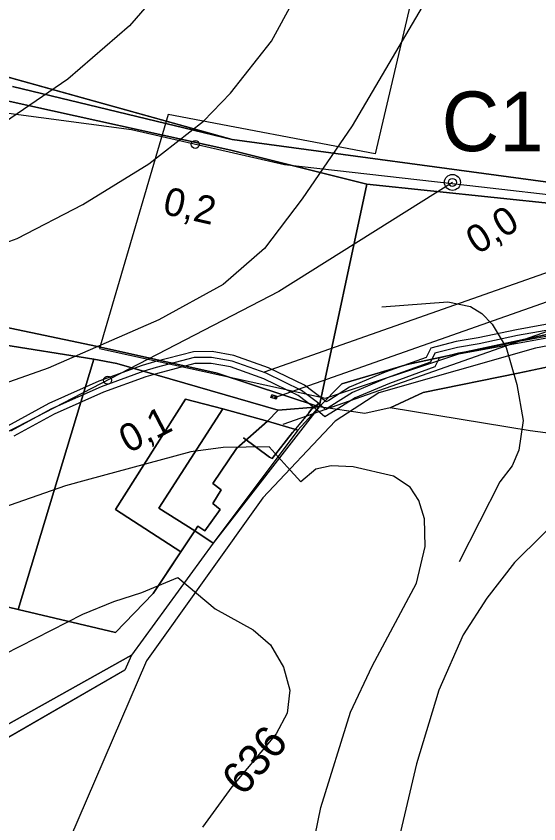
# Model space of a CAD drawing. Extents: x -709418 to -703832, y -1161719 to -1157826.
# Drawn here: x -707328.3 to -707197, y -1160852.4 to -1160649.3 of the extents above; entities that cross this region are included whole.
import ezdxf

# ---------------------------------------------------------------- set-up
doc = ezdxf.new("R2010")
doc.units = 0
for name, color, linetype in [('102_obvod PÚ', 7, 'Continuous'), ('106_zastavitelné plochy', 7, 'Continuous'), ('110_silnice II. třídy a III. třídy', 7, 'Continuous'), ('120_vrstevnice hlavní', 7, 'Continuous'), ('121_vrstevnice hlavní_popis', 7, 'Continuous'), ('122_vrstevnice základní', 7, 'Continuous'), ('124_vrstevnice doplňková', 7, 'Continuous'), ('204_zahrada_KN', 7, 'Continuous'), ('206_TTP_KN', 7, 'Continuous'), ('207_lesní pozemek_KN', 7, 'Continuous'), ('209_zastavěná plocha_KN', 7, 'Continuous'), ('210_ostatní plocha_KN', 7, 'Continuous'), ('301_polní cesta_stav', 7, 'Continuous'), ('302_polní cesta_stav_popis', 7, 'Continuous'), ('311_polní cesta_staničení', 7, 'Continuous'), ('708_el NN nadzemní a podzemní_ E.ON', 7, 'Continuous'), ('717_elektronická komunikace O2', 7, 'Continuous'), ('735_OP sítí TI', 7, 'Continuous'), ('Trasa-Hlavni  staniceni', 7, 'Continuous')]:
    doc.layers.add(name, color=color, linetype=linetype)

# ---------------------------------------------------------------- blocks, each defined once
blk = doc.blocks.new('Elektro - Implicitní$0$NN6301')
for points in [[(0, -0.7), (-0.7, 0)], [(-0.7, -0.7), (-0.7, 0), (0.7, 0), (0.7, -0.7)], [(-0.7, -0.7), (0.7, -0.7)], [(0, -0.7), (0.7, 0)]]:
    blk.add_lwpolyline(points)
blk = doc.blocks.new('_kolecko-HB')
blk.add_circle((0, 0), 0.5)

msp = doc.modelspace()

# ---------------------------------------------------------------- linework, layer by layer
at = {"layer": '102_obvod PÚ'}
for points in [[(-707372.91, -1160652.8), (-707274.07, -1160680.35), (-707329.26, -1160667)], [(-707329.26, -1160667), (-707274.07, -1160680.35), (-707372.91, -1160652.8)], [(-706967.13, -1160843.73), (-707054.56, -1160846.24), (-707070.52, -1160774.23), (-707110.93, -1160765.08), (-707199.13, -1160753.56), (-707234.31, -1160747.78), (-707240.69, -1160749.2), (-707252.18, -1160747.56), (-707262.52, -1160748.35), (-707303.06, -1160736.64), (-707308.84, -1160735.57), (-707327.8, -1160798.49), (-707303.36, -1160804.27), (-707293.87, -1160794.5), (-707283.47, -1160778.71), (-707278.83, -1160781.85), (-707299.31, -1160809.97), (-707301.02, -1160813.75), (-707341.56, -1160837.15), (-707370.67, -1160817.96), (-707379.03, -1160849.56), (-707386.91, -1160884.92)], [(-707327.8, -1160798.49), (-707308.84, -1160735.57), (-707303.06, -1160736.64), (-707262.52, -1160748.35), (-707252.18, -1160747.56), (-707278.83, -1160781.85), (-707283.47, -1160778.71), (-707293.87, -1160794.5), (-707303.36, -1160804.27), (-707327.8, -1160798.49)]]:
    msp.add_lwpolyline(points, dxfattribs=at)
at = {"layer": '106_zastavitelné plochy'}
msp.add_lwpolyline([(-707143.96, -1160643.94), (-707203.3, -1160641.79), (-707228.67, -1160643.51), (-707238.13, -1160683.91), (-707290.16, -1160674.03), (-707307.36, -1160732.91), (-707250.6, -1160745.38), (-707217.06, -1160734.2), (-707117.73, -1160716.15), (-707089.46, -1160706.83), (-707146.29, -1160697.63), (-707149.08, -1160694.92), (-707131.06, -1160645.23), (-707143.96, -1160643.94)], dxfattribs=at)
at = {"layer": '110_silnice II. třídy a III. třídy'}
msp.add_lwpolyline([(-707028.32, -1160686.05), (-707048.83, -1160698.73), (-707085.42, -1160709.51), (-707112.28, -1160716.49), (-707197.84, -1160732.78), (-707237.17, -1160743.98), (-707248.17, -1160751.17), (-707266.36, -1160770.4), (-707295.62, -1160811.38), (-707336.44, -1160906.07)], dxfattribs=at)
at = {"layer": '120_vrstevnice hlavní'}
for points in [[(-707239.58, -1160471.05), (-707235.67, -1160484.94), (-707230.32, -1160508.08), (-707224.97, -1160540.48), (-707222.65, -1160549.74), (-707217.45, -1160563.62), (-707213.4, -1160577.51), (-707212.53, -1160591.4), (-707214.26, -1160609.91), (-707216.87, -1160623.8), (-707221.78, -1160637.68), (-707226.27, -1160646.94), (-707243.92, -1160676.88), (-707256.5, -1160695.25), (-707265.9, -1160707.69), (-707276.32, -1160716.8), (-707292.52, -1160725.63), (-707320.29, -1160737.78), (-707344.3, -1160746.31)], [(-707023.62, -1160699.16), (-707028.9, -1160695.89), (-707035.14, -1160696.56), (-707038.9, -1160689.77), (-707049.51, -1160686.72), (-707065.71, -1160686.28), (-707077.86, -1160687.44), (-707085.96, -1160689.32), (-707098.11, -1160693.52), (-707106.21, -1160697.28), (-707118.36, -1160704.07), (-707123.33, -1160706.91), (-707129.34, -1160709.92), (-707136.11, -1160714.06), (-707134.98, -1160726.48), (-707146.27, -1160736.26), (-707161.76, -1160747.03), (-707168.27, -1160752.24), (-707203.12, -1160786.67), (-707210.07, -1160795.63), (-707216, -1160804.89), (-707222.07, -1160818.78), (-707227.72, -1160837.29), (-707235.38, -1160869.69)]]:
    msp.add_lwpolyline(points, dxfattribs=at)
at = {"layer": '122_vrstevnice základní'}
for points in [[(-707280.22, -1160472.21), (-707271.98, -1160495.64), (-707269.52, -1160504.32), (-707266.62, -1160518.79), (-707265.76, -1160533.25), (-707266.34, -1160554.37), (-707268.79, -1160576.64), (-707275.01, -1160602.1), (-707278.05, -1160611.65), (-707288.03, -1160633.92), (-707295.41, -1160646.65), (-707299.89, -1160651.71), (-707315.37, -1160665.16), (-707351.82, -1160690.04)], [(-707336.49, -1160708.27), (-707328.1, -1160705.23), (-707311.61, -1160696.7), (-707294.97, -1160686.43), (-707281.23, -1160675.72), (-707274.44, -1160668.64), (-707264.17, -1160655.62), (-707258.52, -1160645.2), (-707256.35, -1160640), (-707250.14, -1160620.32), (-707247.53, -1160608.75), (-707246.23, -1160600.07), (-707244.78, -1160574.04), (-707244.64, -1160556.68), (-707246.52, -1160515.6), (-707249.12, -1160502.58), (-707255.78, -1160479.15)], [(-707256.07, -1160869.11), (-707251.73, -1160848.29), (-707244.35, -1160824.27), (-707238.85, -1160812.7), (-707227.71, -1160791.87), (-707225.55, -1160782.62), (-707225.69, -1160775.67), (-707227.14, -1160771.05), (-707229.31, -1160767.72), (-707233.5, -1160764.97), (-707243.63, -1160762.66), (-707249.19, -1160762.37), (-707253.03, -1160763.23), (-707256.79, -1160766.42), (-707260.26, -1160762.66), (-707264.74, -1160757.59), (-707276.32, -1160757.74), (-707284.42, -1160758.89), (-707310.74, -1160765.98), (-707315.95, -1160767.43), (-707338.8, -1160775.38)], [(-707335.33, -1160811.69), (-707311.61, -1160799.68), (-707303.8, -1160796.5), (-707296.72, -1160794.22), (-707287.7, -1160790.45), (-707278.29, -1160798.35), (-707268.79, -1160803.59), (-707264.45, -1160807.35), (-707261.13, -1160812.99), (-707259.54, -1160818.78), (-707260.26, -1160824.56), (-707263.01, -1160829.77), (-707274.15, -1160843.08), (-707281.52, -1160853.2)]]:
    msp.add_lwpolyline(points, dxfattribs=at)
at = {"layer": '124_vrstevnice doplňková'}
msp.add_lwpolyline([(-707236.46, -1160722.37), (-707219.82, -1160721.15), (-707214.12, -1160722.3), (-707211.27, -1160724.03), (-707208.71, -1160726.75), (-707205.18, -1160732.62), (-707202.54, -1160741.96), (-707200.9, -1160750.97), (-707201.99, -1160758.4), (-707203.7, -1160762.37), (-707206.74, -1160766.42), (-707217.01, -1160786.52)], dxfattribs=at)
at = {"layer": '204_zahrada_KN'}
for p, q in [((-707327.8, -1160798.49), (-707308.84, -1160735.57)), ((-707308.84, -1160735.57), (-707303.06, -1160736.64)), ((-707303.06, -1160736.64), (-707262.52, -1160748.35)), ((-707285.78, -1160745.57), (-707303.37, -1160773.36)), ((-707303.37, -1160773.36), (-707285.78, -1160745.57)), ((-707276.36, -1160748), (-707285.78, -1160745.57)), ((-707285.78, -1160745.57), (-707276.36, -1160748)), ((-707276.36, -1160748), (-707292.48, -1160773.03)), ((-707265.13, -1160751.17), (-707276.36, -1160748)), ((-707262.52, -1160748.35), (-707265.13, -1160751.17)), ((-707303.37, -1160773.36), (-707286.95, -1160784)), ((-707286.95, -1160784), (-707303.37, -1160773.36)), ((-707292.48, -1160773.03), (-707283.47, -1160778.71)), ((-707283.47, -1160778.71), (-707286.95, -1160784)), ((-707286.95, -1160784), (-707293.87, -1160794.5)), ((-707293.87, -1160794.5), (-707303.36, -1160804.27)), ((-707303.36, -1160804.27), (-707327.8, -1160798.49))]:
    msp.add_line(p, q, dxfattribs=at)
at = {"layer": '206_TTP_KN'}
for p, q in [((-707274.07, -1160680.35), (-707372.91, -1160652.8)), ((-707330.61, -1160670.57), (-707274.38, -1160682.99)), ((-707154, -1160696.51), (-707274.07, -1160680.35)), ((-707274.38, -1160682.99), (-707240.22, -1160691.57)), ((-707240.22, -1160691.57), (-707252.18, -1160747.56)), ((-707252.18, -1160747.56), (-707240.22, -1160691.57)), ((-707240.22, -1160691.57), (-707160.56, -1160699.93)), ((-707307.9, -1160732.39), (-707450.47, -1160702.52)), ((-707097.65, -1160708.58), (-707230.1, -1160736.86)), ((-707388.32, -1160722.75), (-707308.84, -1160735.57)), ((-707277.81, -1160739.08), (-707307.9, -1160732.39)), ((-707308.84, -1160735.57), (-707327.8, -1160798.49)), ((-707230.1, -1160736.86), (-707246.51, -1160741.72)), ((-707252.18, -1160747.56), (-707277.81, -1160739.08)), ((-707246.51, -1160741.72), (-707252.18, -1160747.56)), ((-707327.8, -1160798.49), (-707376.64, -1160787.21))]:
    msp.add_line(p, q, dxfattribs=at)
msp.add_lwpolyline([(-707234.31, -1160747.78), (-707226.04, -1160743.96), (-707202.13, -1160739.1), (-707165.11, -1160731.2), (-707079.4, -1160713.35), (-707059.84, -1160708.95), (-707048.21, -1160704.45), (-707031.59, -1160693.68), (-707019.9, -1160684.54), (-707014.32, -1160693.26), (-707001.31, -1160724.16), (-707005.22, -1160751.16), (-707009.34, -1160768.26), (-707025.89, -1160772.6), (-707027.13, -1160765.46), (-707047.54, -1160769.57), (-707052.47, -1160770.8), (-707052.65, -1160775.35), (-707110.93, -1160765.08), (-707199.13, -1160753.56), (-707234.31, -1160747.78)], dxfattribs=at)
at = {"layer": '207_lesní pozemek_KN'}
for p, q in [((-707372.91, -1160652.8), (-707274.07, -1160680.35)), ((-707274.07, -1160680.35), (-707329.26, -1160667))]:
    msp.add_line(p, q, dxfattribs=at)
at = {"layer": '209_zastavěná plocha_KN'}
for p, q in [((-707292.48, -1160773.03), (-707276.36, -1160748)), ((-707276.36, -1160748), (-707265.13, -1160751.17)), ((-707265.13, -1160751.17), (-707272.95, -1160758)), ((-707272.95, -1160758), (-707278.88, -1160766.82)), ((-707278.88, -1160766.82), (-707276.81, -1160768.42)), ((-707276.81, -1160768.42), (-707278.91, -1160771.88)), ((-707283.47, -1160778.71), (-707292.48, -1160773.03)), ((-707277.06, -1160773.35), (-707280.95, -1160778.7)), ((-707278.91, -1160771.88), (-707277.06, -1160773.35)), ((-707282.66, -1160777.52), (-707283.47, -1160778.71)), ((-707280.95, -1160778.7), (-707282.66, -1160777.52))]:
    msp.add_line(p, q, dxfattribs=at)
at = {"layer": '210_ostatní plocha_KN'}
for p, q in [((-707329.26, -1160667), (-707274.07, -1160680.35)), ((-707274.38, -1160682.99), (-707330.61, -1160670.57)), ((-707274.07, -1160680.35), (-707154, -1160696.51)), ((-707240.22, -1160691.57), (-707274.38, -1160682.99)), ((-707160.56, -1160699.93), (-707240.22, -1160691.57)), ((-707450.47, -1160702.52), (-707307.9, -1160732.39)), ((-707230.1, -1160736.86), (-707097.65, -1160708.58)), ((-707308.84, -1160735.57), (-707388.32, -1160722.75)), ((-707307.9, -1160732.39), (-707277.81, -1160739.08)), ((-707165.11, -1160731.2), (-707202.13, -1160739.1)), ((-707303.06, -1160736.64), (-707308.84, -1160735.57)), ((-707262.52, -1160748.35), (-707303.06, -1160736.64)), ((-707246.51, -1160741.72), (-707230.1, -1160736.86)), ((-707277.81, -1160739.08), (-707252.18, -1160747.56)), ((-707202.13, -1160739.1), (-707226.04, -1160743.96)), ((-707252.18, -1160747.56), (-707246.51, -1160741.72)), ((-707226.04, -1160743.96), (-707234.31, -1160747.78)), ((-707265.13, -1160751.17), (-707262.52, -1160748.35)), ((-707252.18, -1160747.56), (-707262.52, -1160748.35)), ((-707262.52, -1160748.35), (-707252.18, -1160747.56)), ((-707252.18, -1160747.56), (-707257.52, -1160753.42)), ((-707240.69, -1160749.2), (-707252.18, -1160747.56)), ((-707234.31, -1160747.78), (-707240.69, -1160749.2)), ((-707272.95, -1160758), (-707265.13, -1160751.17)), ((-707265.13, -1160751.17), (-707257.52, -1160753.42)), ((-707257.52, -1160753.42), (-707265.13, -1160751.17)), ((-707257.52, -1160753.42), (-707278.83, -1160781.85)), ((-707278.88, -1160766.82), (-707272.95, -1160758)), ((-707276.81, -1160768.42), (-707278.88, -1160766.82)), ((-707278.91, -1160771.88), (-707276.81, -1160768.42)), ((-707280.95, -1160778.7), (-707277.06, -1160773.35)), ((-707277.06, -1160773.35), (-707278.91, -1160771.88)), ((-707283.47, -1160778.71), (-707282.66, -1160777.52)), ((-707282.66, -1160777.52), (-707280.95, -1160778.7)), ((-707286.95, -1160784), (-707283.47, -1160778.71)), ((-707283.47, -1160778.71), (-707278.83, -1160781.85)), ((-707278.83, -1160781.85), (-707283.47, -1160778.71)), ((-707278.83, -1160781.85), (-707299.31, -1160809.97)), ((-707293.87, -1160794.5), (-707286.95, -1160784)), ((-707376.64, -1160787.21), (-707327.8, -1160798.49)), ((-707303.36, -1160804.27), (-707293.87, -1160794.5)), ((-707327.8, -1160798.49), (-707303.36, -1160804.27)), ((-707341.03, -1160833.31), (-707299.31, -1160809.97)), ((-707299.31, -1160809.97), (-707341.03, -1160833.31)), ((-707299.31, -1160809.97), (-707301.02, -1160813.75)), ((-707301.02, -1160813.75), (-707341.56, -1160837.15))]:
    msp.add_line(p, q, dxfattribs=at)
at = {"layer": '301_polní cesta_stav'}
for points in [[(-707085.42, -1160709.51), (-707119.88, -1160705.05), (-707158.87, -1160698.37), (-707214.33, -1160692), (-707260.88, -1160686.66), (-707299.36, -1160677.92), (-707332.88, -1160673.44), (-707359.79, -1160673.86), (-707378.15, -1160677.28), (-707405.26, -1160689.87), (-707419.36, -1160694.78), (-707437.11, -1160695.04), (-707506.53, -1160672.74), (-707574.71, -1160666.55), (-707597.64, -1160662.21), (-707620.57, -1160644.86), (-707625.53, -1160629.38), (-707610.04, -1160578.58)], [(-707218.69, -1160691.11), (-707262.35, -1160718.51), (-707328.14, -1160752.67), (-707408.59, -1160793.36)]]:
    msp.add_lwpolyline(points, dxfattribs=at)
at = {"layer": '311_polní cesta_staničení'}
msp.add_circle((-707218.69, -1160691.11), 2, dxfattribs=at)
at = {"layer": '708_el NN nadzemní a podzemní_ E.ON'}
msp.add_lwpolyline([(-707055.49, -1160683.99), (-707054.58, -1160683.65), (-707058.78, -1160671.85), (-707132.04, -1160699.04), (-707263.64, -1160745.39)], dxfattribs=at)
at = {"layer": '717_elektronická komunikace O2'}
for points in [[(-707191.82, -1160727.73), (-707202.31, -1160729.64), (-707211.95, -1160731.67), (-707217.46, -1160732.58), (-707223.09, -1160734.04), (-707224.21, -1160736.31), (-707235.09, -1160740.25), (-707243.84, -1160743.96), (-707248.99, -1160747.2), (-707250.57, -1160748.18), (-707252.31, -1160746.68), (-707256.65, -1160743.39), (-707265.51, -1160739.1), (-707274.04, -1160736.07), (-707279.22, -1160735.13), (-707283.61, -1160735.17), (-707293.19, -1160737.68), (-707296.24, -1160738.59), (-707306.99, -1160742.48), (-707319.45, -1160748.05), (-707329.73, -1160753.65)], [(-707252.31, -1160746.68), (-707254.08, -1160748.12), (-707254.8, -1160749.01), (-707258.9, -1160754), (-707263.96, -1160760.5), (-707264.7, -1160760.19), (-707271.24, -1160755.37)], [(-707254.8, -1160749.01), (-707254.08, -1160748.12), (-707252.31, -1160746.68), (-707250.57, -1160748.18), (-707248.99, -1160747.2)], [(-707271.24, -1160755.37), (-707264.7, -1160760.19), (-707263.96, -1160760.5), (-707258.9, -1160754)]]:
    msp.add_lwpolyline(points, dxfattribs=at)
at = {"layer": '735_OP sítí TI'}
for points in [[(-707053.04, -1160690.55), (-707045.67, -1160687.8), (-707054.56, -1160662.82), (-707134.42, -1160692.46), (-707265.97, -1160738.79)], [(-707062.36, -1160682.66), (-707063, -1160680.88), (-707129.66, -1160705.62), (-707261.31, -1160751.99)], [(-707192.1, -1160726.26), (-707202.6, -1160728.17), (-707212.23, -1160730.2), (-707217.77, -1160731.11), (-707224.13, -1160732.76), (-707225.29, -1160735.11), (-707235.64, -1160738.85), (-707244.54, -1160742.63), (-707249.78, -1160745.93), (-707250.42, -1160746.32), (-707251.37, -1160745.51), (-707255.86, -1160742.1), (-707264.93, -1160737.71), (-707273.65, -1160734.62), (-707279.09, -1160733.63), (-707283.81, -1160733.67), (-707293.59, -1160736.24), (-707296.71, -1160737.16), (-707307.55, -1160741.09), (-707320.12, -1160746.7), (-707330.51, -1160752.37)], [(-707191.54, -1160729.2), (-707202.02, -1160731.11), (-707211.67, -1160733.14), (-707217.15, -1160734.05), (-707222.05, -1160735.32), (-707223.13, -1160737.51), (-707234.54, -1160741.65), (-707243.14, -1160745.29), (-707248.2, -1160748.47), (-707250.72, -1160750.04), (-707253.25, -1160747.85), (-707257.44, -1160744.68), (-707266.09, -1160740.49), (-707274.43, -1160737.52), (-707279.35, -1160736.63), (-707283.41, -1160736.67), (-707292.79, -1160739.12), (-707295.77, -1160740.02), (-707306.43, -1160743.87), (-707318.78, -1160749.4), (-707328.95, -1160754.93)]]:
    msp.add_lwpolyline(points, dxfattribs=at)

# ---------------------------------------------------------------- block references
at = {"layer": '708_el NN nadzemní a podzemní_ E.ON', "rotation": 162.26737227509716}
msp.add_blockref('Elektro - Implicitní$0$NN6301', (-707263.64, -1160745.39), dxfattribs=at)
at = {"layer": 'Trasa-Hlavni  staniceni'}
for p, xscale, yscale, rotation in [((-707283.32, -1160681.56), 1.9999999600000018, 1.999999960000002, 167.1939812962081), ((-707218.69, -1160691.11), 1.9999999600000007, 1.9999999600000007, -147.8907060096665), ((-707305.35, -1160740.84), 1.9999999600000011, 1.9999999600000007, -152.55759827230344)]:
    msp.add_blockref('_kolecko-HB', p, dxfattribs=dict(at, xscale=xscale, yscale=yscale, rotation=rotation))

# ---------------------------------------------------------------- texts
at = {"layer": '121_vrstevnice hlavní_popis'}
msp.add_text('636', height=8, rotation=49.4784, dxfattribs=at).set_placement((-707271.26, -1160845.68))
at = {"layer": '302_polní cesta_stav_popis'}
msp.add_text('C16', height=15, dxfattribs=at).set_placement((-707221.41, -1160683.26))
at = {"layer": 'Trasa-Hlavni  staniceni'}
for s, rotation, p in [('0,2', 347.194, (-707291.78, -1160698.95)), ('0,0', 32.1093, (-707212.42, -1160709.4)), ('0,1', 27.4424, (-707300.12, -1160759.33))]:
    msp.add_text(s, height=7, rotation=rotation, dxfattribs=at).set_placement(p)

doc.saveas('drawing.dxf')
